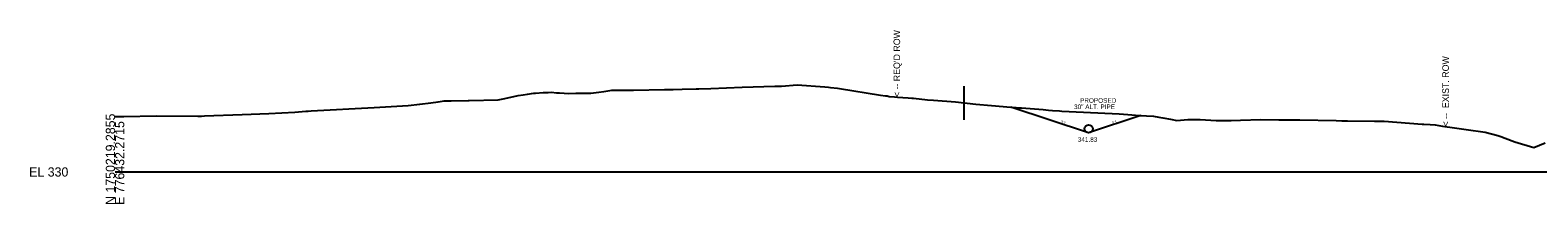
# Model space of a CAD drawing. Extents: x 776426 to 854588, y 1736205 to 1756790.
# Drawn here: x 804645.1 to 805101.4, y 1748205.1 to 1748257.8 of the extents above; entities that cross this region are included whole.
import ezdxf

# ---------------------------------------------------------------- set-up
doc = ezdxf.new("R2010")
doc.units = 0
for name, color, linetype in [('DTM CONTOURS_MAJOR_TX', 7, 'Continuous'), ('DTM_X_FLOW_ARROWS', 7, 'Continuous'), ('X_TRANS_EOP', 7, 'Continuous'), ('XS_M_SHAPES_EARTHWORK', 7, 'Continuous'), ('XS_P_DRAINAGE', 7, 'Continuous'), ('XS_P_FINISHED_GRADE', 7, 'Continuous'), ('XS_P_ROW', 7, 'Continuous'), ('XS_P_TX_DCH', 7, 'Continuous'), ('XS_P_TX_FS_BS', 7, 'Continuous'), ('XS_X_ROW', 7, 'Continuous')]:
    doc.layers.add(name, color=color, linetype=linetype)

msp = doc.modelspace()

# ---------------------------------------------------------------- linework, layer by layer
at = {"layer": 'DTM CONTOURS_MAJOR_TX'}
msp.add_line((804670.79, 1748214.76), (805170.79, 1748214.76), dxfattribs=at)
at = {"layer": 'DTM_X_FLOW_ARROWS'}
msp.add_lwpolyline([(804670.79, 1748231.61), (804673.46, 1748231.59), (804683.24, 1748231.78), (804695.83, 1748231.72), (804696.92, 1748231.72), (804697.83, 1748231.76), (804709.25, 1748232.2), (804717.33, 1748232.45), (804725.26, 1748232.89), (804728.53, 1748233.17), (804729.24, 1748233.21), (804730.14, 1748233.27), (804749.2, 1748234.33), (804750.91, 1748234.4), (804759.52, 1748234.88), (804763.05, 1748235.33), (804766.4, 1748235.72), (804768.58, 1748236.06), (804770.37, 1748236.29), (804772.55, 1748236.37), (804777.65, 1748236.46), (804778, 1748236.47), (804786.8, 1748236.64), (804788.8, 1748237.07), (804792.78, 1748237.9), (804794.34, 1748238.16), (804795.66, 1748238.39), (804796.8, 1748238.57), (804797.5, 1748238.61), (804798.07, 1748238.64), (804800.37, 1748238.88), (804801.88, 1748238.86), (804802.88, 1748238.93), (804804.43, 1748238.79), (804805.32, 1748238.77), (804808.13, 1748238.51), (804810.26, 1748238.6), (804810.56, 1748238.61), (804813.08, 1748238.63), (804814.84, 1748238.67), (804817.23, 1748238.92), (804818.79, 1748239.16), (804821.14, 1748239.55), (804826.09, 1748239.51), (804826.91, 1748239.56), (804827.71, 1748239.58), (804837.08, 1748239.73), (804839.74, 1748239.8), (804842.44, 1748239.88), (804846.67, 1748239.95), (804847.53, 1748239.98), (804851.15, 1748240.11), (804860.6, 1748240.5), (804870.47, 1748240.74), (804871.42, 1748240.76), (804872.47, 1748240.79), (804877.23, 1748241.16), (804885.61, 1748240.55), (804886.72, 1748240.48), (804887.33, 1748240.38), (804889.43, 1748240.15), (804890.1, 1748240.07), (804902.51, 1748238.02), (804904.02, 1748237.83), (804904.46, 1748237.8), (804905.13, 1748237.68), (804906.74, 1748237.51), (804907.58, 1748237.42), (804909.24, 1748237.35), (804910.88, 1748237.22), (804911.93, 1748237.16), (804912.52, 1748237.15), (804916.74, 1748236.65), (804918.52, 1748236.54), (804925.21, 1748236.05), (804931.32, 1748235.29), (804936.05, 1748234.86), (804941.96, 1748234.43), (804943.15, 1748234.31), (804943.54, 1748234.27), (804944.39, 1748234.21), (804945.19, 1748234.16), (804951.75, 1748233.65), (804953.29, 1748233.52), (804954.55, 1748233.41), (804956.69, 1748233.3), (804957.36, 1748233.24), (804959.6, 1748233.13), (804974.77, 1748232.36), (804977.39, 1748232.18), (804980.88, 1748231.89), (804985.13, 1748231.67), (804986.69, 1748231.4), (804987.93, 1748231.16), (804990.23, 1748230.75), (804992.2, 1748230.4), (804995.51, 1748230.62), (804996.59, 1748230.68), (804998.26, 1748230.71), (804999.27, 1748230.64), (805004.1, 1748230.4), (805008.65, 1748230.35), (805011.43, 1748230.47), (805017.61, 1748230.66), (805023.03, 1748230.59), (805025.42, 1748230.57), (805027.03, 1748230.52), (805029.44, 1748230.58), (805040.4, 1748230.32), (805042.13, 1748230.28), (805043.87, 1748230.22), (805051.97, 1748230.17), (805053.72, 1748230.16), (805054.47, 1748230.16), (805054.98, 1748230.16), (805066.41, 1748229.29), (805066.98, 1748229.24), (805068.88, 1748229.11), (805070.37, 1748229), (805072.63, 1748228.66), (805076.26, 1748228.18), (805079.75, 1748227.68), (805085.55, 1748226.84), (805089.29, 1748225.77), (805090.29, 1748225.5), (805093.69, 1748224.17), (805094.49, 1748223.86), (805100.22, 1748222.16), (805103.67, 1748223.58)], dxfattribs=at)
at = {"layer": 'X_TRANS_EOP'}
for p, q in [((804927.74, 1748240.73), (804927.74, 1748235.73)), ((804927.74, 1748235.58), (804927.74, 1748230.58))]:
    msp.add_line(p, q, dxfattribs=at)
at = {"layer": 'XS_M_SHAPES_EARTHWORK'}
msp.add_lwpolyline([(804977.39, 1748232.18), (804980.88, 1748231.89), (804981.32, 1748231.87), (804965.48, 1748226.59), (804941.94, 1748234.44), (804941.96, 1748234.43), (804943.15, 1748234.31), (804943.54, 1748234.27), (804944.39, 1748234.21), (804945.19, 1748234.16), (804951.75, 1748233.65), (804953.29, 1748233.52), (804954.55, 1748233.41), (804956.69, 1748233.3), (804957.36, 1748233.24), (804959.6, 1748233.13), (804974.77, 1748232.36)], close=True, dxfattribs=at)
at = {"layer": 'XS_P_DRAINAGE'}
msp.add_circle((804965.48, 1748227.84), 1.25, dxfattribs=at)
at = {"layer": 'XS_P_FINISHED_GRADE'}
for p, q in [((804965.48, 1748226.59), (804941.94, 1748234.44)), ((804981.32, 1748231.87), (804965.48, 1748226.59))]:
    msp.add_line(p, q, dxfattribs=at)

# ---------------------------------------------------------------- texts
at = {"layer": 'DTM CONTOURS_MAJOR_TX'}
for s, p in [('N 1750219.2855', (804670.79, 1748204.76)), ('E 776432.2715', (804673.59, 1748204.76))]:
    msp.add_text(s, height=2.8, rotation=90, dxfattribs=at).set_placement(p)
msp.add_text('EL 330', height=2.8, dxfattribs=at).set_placement((804644.79, 1748213.36))
at = {"layer": 'XS_P_DRAINAGE'}
for s, p in [('30" ALT. PIPE', (804961.08, 1748233.82)), ('PROPOSED', (804962.89, 1748235.72))]:
    msp.add_text(s, height=1.4, rotation=360, dxfattribs=at).set_placement(p)
at = {"layer": 'XS_P_ROW'}
msp.add_text("< -- REQ'D ROW", height=2, rotation=90, dxfattribs=at).set_placement((804908.42, 1748237.44))
at = {"layer": 'XS_P_TX_DCH'}
msp.add_text('341.83', height=1.4, dxfattribs=at).set_placement((804962.2, 1748223.89))
at = {"layer": 'XS_P_TX_FS_BS'}
for rotation, p in [(341.5651, (804956.98, 1748229.66)), (18.4349, (804972.69, 1748229.23))]:
    msp.add_text('3:1', height=0.8, rotation=rotation, dxfattribs=at).set_placement(p)
at = {"layer": 'XS_X_ROW'}
msp.add_text('< --  EXIST. ROW', height=2, rotation=90, dxfattribs=at).set_placement((805074.53, 1748228.54))

doc.saveas('drawing.dxf')
